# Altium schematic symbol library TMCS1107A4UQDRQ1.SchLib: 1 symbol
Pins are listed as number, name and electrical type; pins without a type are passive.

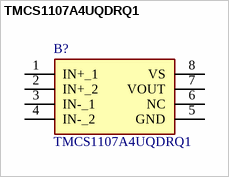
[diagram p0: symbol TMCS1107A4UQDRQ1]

## TMCS1107A4UQDRQ1
designator B?
Manufacturer_Name: Texas Instruments; Geometry.Height: 1.75mm
footprint SOIC127P600X175-8N
pins: 1 IN+_1, 2 IN+_2, 3 IN-_1, 4 IN-_2, 5 GND, 6 NC, 7 VOUT, 8 VS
